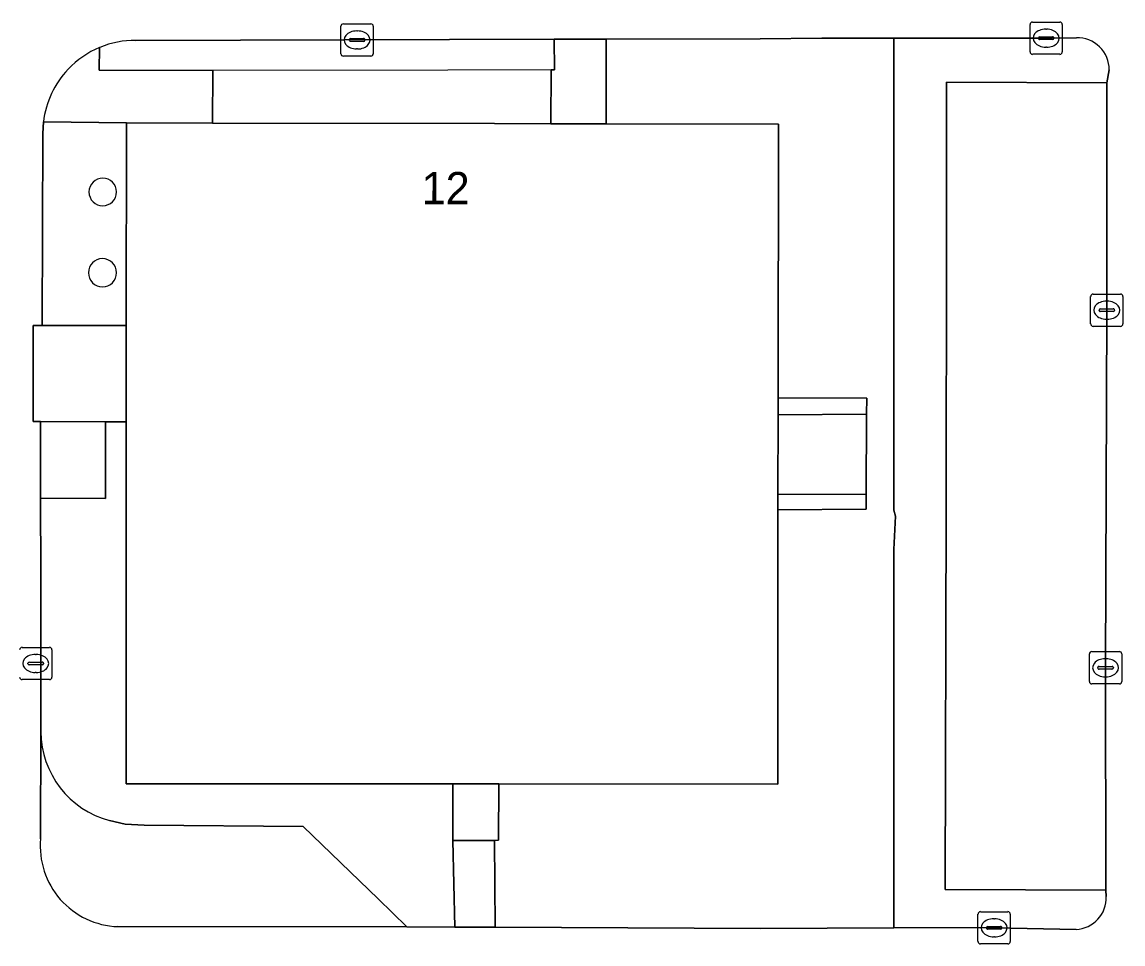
# Model space of a CAD drawing. Extents: x 161477 to 163040, y 383680 to 384871.
# Drawn here: x 161894.85 to 161928.97, y 384085.24 to 384113.8 of the extents above; entities that cross this region are included whole.
import ezdxf

# ---------------------------------------------------------------- set-up
doc = ezdxf.new("R2010")
doc.units = 0
for name, color, linetype in [('IMGEO_Dek', 7, 'Continuous'), ('IMGEO_Groenvoorziening', 7, 'Continuous'), ('IMGEO_Kolk', 7, 'Continuous'), ('IMGEO_Opslagtank', 7, 'Continuous'), ('IMGEO_Pand', 7, 'Continuous'), ('IMGEO_Pand_nummerreeks', 7, 'Continuous'), ('IMGEO_Parkeervlak_open', 7, 'Continuous'), ('IMGEO_Rijbaan_lokaal_open', 7, 'Continuous'), ('IMGEO_Voetpad_halfverhard', 7, 'Continuous'), ('IMGEO_Voetpad_op_trap', 7, 'Continuous'), ('IMGEO_Voetpad_open', 7, 'Continuous')]:
    doc.layers.add(name, color=color, linetype=linetype)

msp = doc.modelspace()

# ---------------------------------------------------------------- linework, layer by layer
at = {"layer": 'IMGEO_Dek'}
msp.add_lwpolyline([(161911.242, 384112.317), (161908.043, 384112.311), (161900.763, 384112.296), (161900.748, 384110.668), (161909.493, 384110.653), (161911.237, 384110.65)], close=True, dxfattribs=at)
at = {"layer": 'IMGEO_Groenvoorziening'}
for points in [[(161897.254, 384113.012), (161897.243, 384112.304), (161900.763, 384112.296), (161900.748, 384110.668), (161909.493, 384110.653), (161911.237, 384110.65), (161911.242, 384112.317), (161911.352, 384112.315), (161911.338, 384113.266)], [(161911.338, 384113.266), (161898.379, 384113.23)], [(161927.523, 384113.312), (161926.587, 384113.3), (161921.866, 384113.297), (161921.866, 384101.655), (161921.866, 384099.154), (161921.866, 384098.677), (161921.918, 384098.494), (161921.866, 384097.461), (161921.866, 384085.737), (161924.475, 384085.751), (161927.512, 384085.687)], [(161923.503, 384107.023), (161923.498, 384111.939), (161928.47, 384111.914), (161928.542, 384112.318)], [(161928.451, 384086.709), (161928.44, 384086.908), (161923.462, 384086.921), (161923.483, 384098.676), (161923.503, 384107.023)]]:
    msp.add_lwpolyline(points, dxfattribs=at)
for centre, radius, start, end in [((161898.35, 384110.369), 2.861, 89.4148, 112.5186), ((161927.55, 384112.32), 0.992, 359.8798, 91.5432), ((161927.46, 384086.677), 0.991, 272.9889, 1.8583)]:
    msp.add_arc(centre, radius, start, end, dxfattribs=at)
at = {"layer": 'IMGEO_Kolk'}
for p, q in [((161926.161, 384113.799), (161927.013, 384113.799)), ((161904.731, 384112.818), (161904.731, 384113.67)), ((161904.806, 384113.744), (161905.658, 384113.744)), ((161905.219, 384113.524), (161905.244, 384113.524)), ((161905.732, 384113.67), (161905.732, 384112.818)), ((161926.086, 384112.873), (161926.086, 384113.725)), ((161926.574, 384113.579), (161926.599, 384113.579)), ((161927.087, 384113.725), (161927.087, 384112.873)), ((161904.99, 384113.238), (161904.99, 384113.25)), ((161905.428, 384113.201), (161905.03, 384113.201)), ((161905.033, 384113.287), (161905.431, 384113.287)), ((161905.474, 384113.25), (161905.474, 384113.238)), ((161926.345, 384113.293), (161926.345, 384113.305)), ((161926.783, 384113.256), (161926.385, 384113.256)), ((161926.388, 384113.342), (161926.786, 384113.342)), ((161926.829, 384113.305), (161926.829, 384113.293)), ((161905.658, 384112.744), (161904.806, 384112.744)), ((161905.242, 384112.964), (161905.217, 384112.964)), ((161927.013, 384112.799), (161926.161, 384112.799)), ((161926.597, 384113.019), (161926.572, 384113.019)), ((161927.966, 384104.446), (161927.966, 384105.298)), ((161928.041, 384105.372), (161928.893, 384105.372)), ((161928.967, 384105.298), (161928.967, 384104.446)), ((161928.268, 384104.915), (161928.666, 384104.915)), ((161928.454, 384105.152), (161928.479, 384105.152)), ((161928.225, 384104.866), (161928.225, 384104.878)), ((161928.663, 384104.829), (161928.265, 384104.829)), ((161928.477, 384104.592), (161928.452, 384104.592)), ((161928.709, 384104.878), (161928.709, 384104.866)), ((161928.893, 384104.372), (161928.041, 384104.372)), ((161894.848, 384094.428), (161895.7, 384094.428)), ((161895.774, 384094.354), (161895.774, 384093.502)), ((161895.075, 384093.971), (161895.473, 384093.971)), ((161895.261, 384094.208), (161895.286, 384094.208)), ((161927.928, 384093.37), (161927.928, 384094.222)), ((161928.003, 384094.296), (161928.855, 384094.296)), ((161928.416, 384094.076), (161928.441, 384094.076)), ((161928.929, 384094.222), (161928.929, 384093.37)), ((161895.032, 384093.922), (161895.032, 384093.934)), ((161895.47, 384093.885), (161895.072, 384093.885)), ((161895.284, 384093.648), (161895.259, 384093.648)), ((161895.516, 384093.934), (161895.516, 384093.922)), ((161928.187, 384093.79), (161928.187, 384093.802)), ((161928.625, 384093.753), (161928.227, 384093.753)), ((161928.23, 384093.839), (161928.628, 384093.839)), ((161928.671, 384093.802), (161928.671, 384093.79)), ((161895.7, 384093.428), (161894.848, 384093.428)), ((161928.855, 384093.296), (161928.003, 384093.296)), ((161928.439, 384093.516), (161928.414, 384093.516)), ((161924.474, 384085.313), (161924.474, 384086.165)), ((161924.549, 384086.239), (161925.401, 384086.239)), ((161925.475, 384086.165), (161925.475, 384085.313)), ((161924.776, 384085.782), (161925.174, 384085.782)), ((161924.962, 384086.019), (161924.987, 384086.019)), ((161924.733, 384085.733), (161924.733, 384085.745)), ((161925.171, 384085.696), (161924.773, 384085.696)), ((161924.985, 384085.459), (161924.96, 384085.459)), ((161925.217, 384085.745), (161925.217, 384085.733)), ((161925.401, 384085.239), (161924.549, 384085.239))]:
    msp.add_line(p, q, dxfattribs=at)
for points in [[(161926.161, 384113.799), (161927.013, 384113.799)], [(161904.731, 384112.818), (161904.731, 384113.67)], [(161904.806, 384113.744), (161905.658, 384113.744)], [(161905.732, 384113.67), (161905.732, 384112.818)], [(161926.086, 384112.873), (161926.086, 384113.725)], [(161927.087, 384113.725), (161927.087, 384112.873)], [(161905.658, 384112.744), (161904.806, 384112.744)], [(161927.013, 384112.799), (161926.161, 384112.799)], [(161927.966, 384104.446), (161927.966, 384105.298)], [(161928.041, 384105.372), (161928.893, 384105.372)], [(161928.967, 384105.298), (161928.967, 384104.446)], [(161928.893, 384104.372), (161928.041, 384104.372)], [(161894.848, 384094.428), (161895.7, 384094.428)], [(161895.774, 384094.354), (161895.774, 384093.502)], [(161927.928, 384093.37), (161927.928, 384094.222)], [(161928.003, 384094.296), (161928.855, 384094.296)], [(161928.929, 384094.222), (161928.929, 384093.37)], [(161895.7, 384093.428), (161894.848, 384093.428)], [(161928.855, 384093.296), (161928.003, 384093.296)], [(161924.474, 384085.313), (161924.474, 384086.165)], [(161924.549, 384086.239), (161925.401, 384086.239)], [(161925.475, 384086.165), (161925.475, 384085.313)], [(161925.401, 384085.239), (161924.549, 384085.239)]]:
    msp.add_lwpolyline(points, dxfattribs=at)
for centre, radius, start, end in [((161926.163, 384113.723), 0.0765, 91.552, 178.448), ((161926.163, 384113.723), 0.0765, 91.552, 178.448), ((161927.011, 384113.723), 0.0765, 1.552, 88.448), ((161927.011, 384113.723), 0.0765, 1.552, 88.448), ((161904.808, 384113.668), 0.0765, 91.552, 178.448), ((161904.808, 384113.668), 0.0765, 91.552, 178.448), ((161905.656, 384113.668), 0.0765, 1.552, 88.448), ((161905.656, 384113.668), 0.0765, 1.552, 88.448), ((161905.03, 384113.247), 0.0403, 85.8775, 175.7526), ((161905.027, 384113.237), 0.0366, 178.938, 274.7102), ((161905.431, 384113.244), 0.043, 264.8664, 352.4533), ((161905.435, 384113.249), 0.0386, 1.7309, 96.639), ((161926.385, 384113.302), 0.0403, 85.8775, 175.7526), ((161926.382, 384113.292), 0.0366, 178.938, 274.7102), ((161926.786, 384113.299), 0.043, 264.8664, 352.4533), ((161926.79, 384113.304), 0.0386, 1.7309, 96.639), ((161904.808, 384112.82), 0.0765, 181.552, 268.448), ((161904.808, 384112.82), 0.0765, 181.552, 268.448), ((161905.656, 384112.82), 0.0765, 271.552, 358.448), ((161905.656, 384112.82), 0.0765, 271.552, 358.448), ((161926.163, 384112.875), 0.0765, 181.552, 268.448), ((161926.163, 384112.875), 0.0765, 181.552, 268.448), ((161927.011, 384112.875), 0.0765, 271.552, 358.448), ((161927.011, 384112.875), 0.0765, 271.552, 358.448), ((161928.043, 384105.296), 0.0765, 91.552, 178.448), ((161928.043, 384105.296), 0.0765, 91.552, 178.448), ((161928.891, 384105.296), 0.0765, 1.552, 88.448), ((161928.891, 384105.296), 0.0765, 1.552, 88.448), ((161928.265, 384104.875), 0.0403, 85.8775, 175.7526), ((161928.67, 384104.877), 0.0386, 1.7309, 96.639), ((161928.262, 384104.865), 0.0366, 178.938, 274.7102), ((161928.666, 384104.872), 0.043, 264.8664, 352.4533), ((161928.043, 384104.448), 0.0765, 181.552, 268.448), ((161928.043, 384104.448), 0.0765, 181.552, 268.448), ((161928.891, 384104.448), 0.0765, 271.552, 358.448), ((161928.891, 384104.448), 0.0765, 271.552, 358.448), ((161894.85, 384094.352), 0.0765, 91.552, 178.448), ((161894.85, 384094.352), 0.0765, 91.552, 178.448), ((161895.698, 384094.352), 0.0765, 1.552, 88.448), ((161895.698, 384094.352), 0.0765, 1.552, 88.448), ((161895.072, 384093.931), 0.0403, 85.8775, 175.7526), ((161895.477, 384093.933), 0.0386, 1.7309, 96.639), ((161928.005, 384094.22), 0.0765, 91.552, 178.448), ((161928.005, 384094.22), 0.0765, 91.552, 178.448), ((161928.853, 384094.22), 0.0765, 1.552, 88.448), ((161928.853, 384094.22), 0.0765, 1.552, 88.448), ((161895.069, 384093.921), 0.0366, 178.938, 274.7102), ((161895.473, 384093.928), 0.043, 264.8664, 352.4533), ((161928.227, 384093.799), 0.0403, 85.8775, 175.7526), ((161928.224, 384093.789), 0.0366, 178.938, 274.7102), ((161928.628, 384093.796), 0.043, 264.8664, 352.4533), ((161928.632, 384093.801), 0.0386, 1.7309, 96.639), ((161894.85, 384093.504), 0.0765, 181.552, 268.448), ((161894.85, 384093.504), 0.0765, 181.552, 268.448), ((161895.698, 384093.504), 0.0765, 271.552, 358.448), ((161895.698, 384093.504), 0.0765, 271.552, 358.448), ((161928.005, 384093.372), 0.0765, 181.552, 268.448), ((161928.005, 384093.372), 0.0765, 181.552, 268.448), ((161928.853, 384093.372), 0.0765, 271.552, 358.448), ((161928.853, 384093.372), 0.0765, 271.552, 358.448), ((161924.551, 384086.163), 0.0765, 91.552, 178.448), ((161924.551, 384086.163), 0.0765, 91.552, 178.448), ((161925.399, 384086.163), 0.0765, 1.552, 88.448), ((161925.399, 384086.163), 0.0765, 1.552, 88.448), ((161924.773, 384085.742), 0.0403, 85.8775, 175.7526), ((161925.178, 384085.744), 0.0386, 1.7309, 96.639), ((161924.77, 384085.732), 0.0366, 178.938, 274.7102), ((161925.174, 384085.739), 0.043, 264.8664, 352.4533), ((161924.551, 384085.315), 0.0765, 181.552, 268.448), ((161924.551, 384085.315), 0.0765, 181.552, 268.448), ((161925.399, 384085.315), 0.0765, 271.552, 358.448), ((161925.399, 384085.315), 0.0765, 271.552, 358.448)]:
    msp.add_arc(centre, radius, start, end, dxfattribs=at)
for centre, major_axis, ratio, start_param, end_param in [((161905.218, 384113.244), (-0.387, 0.002), 0.722429, 4.712389, 7.853982), ((161905.243, 384113.244), (-0.39, 0.002), 0.717154, 1.570796, 4.712389), ((161926.573, 384113.299), (-0.387, 0.002), 0.722429, 4.712389, 7.853982), ((161926.598, 384113.299), (-0.39, 0.002), 0.717154, 1.570796, 4.712389), ((161928.453, 384104.872), (-0.387, 0.002), 0.722429, 4.712389, 7.853982), ((161928.478, 384104.872), (-0.39, 0.002), 0.717154, 1.570796, 4.712389), ((161895.26, 384093.928), (-0.387, 0.002), 0.722429, 4.712389, 7.853982), ((161895.285, 384093.928), (-0.39, 0.002), 0.717154, 1.570796, 4.712389), ((161928.415, 384093.796), (-0.387, 0.002), 0.722429, 4.712389, 7.853982), ((161928.44, 384093.796), (-0.39, 0.002), 0.717154, 1.570796, 4.712389), ((161924.961, 384085.739), (-0.387, 0.002), 0.722429, 4.712389, 7.853982), ((161924.986, 384085.739), (-0.39, 0.002), 0.717154, 1.570796, 4.712389)]:
    msp.add_ellipse(centre, major_axis=major_axis, ratio=ratio, start_param=start_param, end_param=end_param, dxfattribs=at)
at = {"layer": 'IMGEO_Opslagtank'}
for centre, radius, start, end in [((161897.351, 384108.535), 0.428, 359.933, 269.933), ((161897.35, 384108.536), 0.428, 270.0648, 359.8012), ((161897.342, 384106.033), 0.437, 90.0656, 359.9344), ((161897.341, 384106.032), 0.437, 0.0025, 89.9975)]:
    msp.add_arc(centre, radius, start, end, dxfattribs=at)
at = {"layer": 'IMGEO_Pand'}
msp.add_lwpolyline([(161918.278, 384101.63), (161918.279, 384102.154), (161918.288, 384110.637), (161912.952, 384110.647), (161911.237, 384110.65), (161909.493, 384110.653), (161900.748, 384110.668), (161898.081, 384110.673), (161898.08, 384104.395), (161898.079, 384101.41), (161898.078, 384096.699), (161898.078, 384094.245), (161898.077, 384090.199), (161908.204, 384090.196), (161909.624, 384090.196), (161918.266, 384090.194), (161918.275, 384098.69), (161918.276, 384099.17)], close=True, dxfattribs=at)
at = {"layer": 'IMGEO_Parkeervlak_open'}
msp.add_lwpolyline([(161923.498, 384111.939), (161923.503, 384107.023), (161923.483, 384098.676), (161923.462, 384086.921), (161928.44, 384086.908), (161928.429, 384093.797), (161928.467, 384104.873), (161928.47, 384111.914)], close=True, dxfattribs=at)
for points in [[(161895.426, 384091.816), (161895.423, 384088.499)], [(161897.819, 384085.777), (161906.777, 384085.765), (161905.88, 384086.635), (161903.562, 384088.881), (161898.637, 384088.917), (161898.042, 384088.951), (161897.559, 384089.06)]]:
    msp.add_lwpolyline(points, dxfattribs=at)
for centre, radius, start, end in [((161898.31, 384091.844), 2.884, 180.5619, 254.9141), ((161897.905, 384088.268), 2.493, 174.6836, 268.0271)]:
    msp.add_arc(centre, radius, start, end, dxfattribs=at)
at = {"layer": 'IMGEO_Rijbaan_lokaal_open'}
for points in [[(161898.379, 384113.23), (161911.338, 384113.266), (161912.946, 384113.27), (161917.724, 384113.283), (161919.637, 384113.296), (161921.866, 384113.297), (161926.587, 384113.3), (161927.523, 384113.312)], [(161928.542, 384112.318), (161928.47, 384111.914), (161928.467, 384104.873), (161928.429, 384093.797), (161928.44, 384086.908), (161928.451, 384086.709)], [(161895.491, 384110.351), (161895.511, 384110.71)], [(161895.423, 384088.499), (161895.426, 384091.816), (161895.427, 384091.877), (161895.429, 384094.247), (161895.426, 384096.705), (161895.424, 384099.051), (161895.422, 384101.427), (161895.192, 384101.427), (161895.189, 384104.397), (161895.469, 384104.397), (161895.491, 384110.351)], [(161927.512, 384085.687), (161924.475, 384085.751), (161921.866, 384085.737), (161917.738, 384085.714), (161909.516, 384085.763), (161908.266, 384085.762), (161906.777, 384085.765), (161897.819, 384085.777)]]:
    msp.add_lwpolyline(points, dxfattribs=at)
for centre, radius, start, end in [((161898.35, 384110.369), 2.861, 89.4148, 112.5186), ((161927.55, 384112.32), 0.992, 359.8798, 91.5432), ((161898.349, 384110.382), 2.849, 112.6072, 136.7222), ((161898.348, 384110.368), 2.857, 136.506, 173.1325), ((161897.905, 384088.268), 2.493, 174.6836, 268.0271), ((161927.46, 384086.677), 0.991, 272.9889, 1.8583)]:
    msp.add_arc(centre, radius, start, end, dxfattribs=at)
at = {"layer": 'IMGEO_Voetpad_halfverhard'}
for points in [[(161921.866, 384097.461), (161921.918, 384098.494), (161921.866, 384098.677), (161921.866, 384099.154), (161921.866, 384101.655), (161921.866, 384113.297), (161919.637, 384113.296), (161917.724, 384113.283), (161912.946, 384113.27), (161912.948, 384112.29), (161912.952, 384110.647), (161918.288, 384110.637), (161918.279, 384102.154), (161921.026, 384102.142), (161921.023, 384101.649), (161921.009, 384099.158), (161921.006, 384098.71), (161918.275, 384098.69), (161918.266, 384090.194), (161909.624, 384090.196), (161909.615, 384088.454), (161909.494, 384088.441), (161909.516, 384085.763), (161917.738, 384085.714), (161921.866, 384085.737)], [(161898.081, 384110.673), (161895.511, 384110.71), (161895.491, 384110.351), (161895.469, 384104.397), (161898.08, 384104.395)]]:
    msp.add_lwpolyline(points, close=True, dxfattribs=at)
for points in [[(161898.078, 384096.699), (161898.079, 384101.41), (161897.439, 384101.411), (161897.434, 384099.035), (161895.424, 384099.051), (161895.426, 384096.705), (161895.429, 384094.247), (161895.427, 384091.877), (161895.426, 384091.816)], [(161897.559, 384089.06), (161898.042, 384088.951), (161898.637, 384088.917), (161903.562, 384088.881), (161905.88, 384086.635), (161906.777, 384085.765), (161908.266, 384085.762), (161908.195, 384088.44), (161908.204, 384090.196), (161898.077, 384090.199), (161898.078, 384094.245), (161898.078, 384096.699)]]:
    msp.add_lwpolyline(points, dxfattribs=at)
for centre, radius, start, end in [((161897.351, 384108.535), 0.428, 359.933, 269.933), ((161897.35, 384108.536), 0.428, 270.0648, 359.8012), ((161897.342, 384106.033), 0.437, 90.0656, 359.9344), ((161897.341, 384106.032), 0.437, 0.0025, 89.9975), ((161898.31, 384091.844), 2.884, 180.5619, 254.9141)]:
    msp.add_arc(centre, radius, start, end, dxfattribs=at)
at = {"layer": 'IMGEO_Voetpad_op_trap'}
for points in [[(161918.279, 384102.154), (161918.278, 384101.63), (161921.023, 384101.649), (161921.026, 384102.142)], [(161921.009, 384099.158), (161918.276, 384099.17), (161918.275, 384098.69), (161921.006, 384098.71)], [(161909.624, 384090.196), (161908.204, 384090.196), (161908.195, 384088.44), (161909.494, 384088.441), (161909.615, 384088.454)]]:
    msp.add_lwpolyline(points, close=True, dxfattribs=at)
at = {"layer": 'IMGEO_Voetpad_open'}
for points in [[(161912.948, 384112.29), (161912.946, 384113.27), (161911.338, 384113.266), (161911.352, 384112.315), (161911.242, 384112.317), (161911.237, 384110.65), (161912.952, 384110.647)], [(161911.242, 384112.317), (161908.043, 384112.311), (161900.763, 384112.296), (161900.748, 384110.668), (161909.493, 384110.653), (161911.237, 384110.65)], [(161898.08, 384104.395), (161895.469, 384104.397), (161895.189, 384104.397), (161895.192, 384101.427), (161895.422, 384101.427), (161897.439, 384101.411), (161898.079, 384101.41)], [(161921.023, 384101.649), (161918.278, 384101.63), (161918.276, 384099.17), (161921.009, 384099.158)], [(161897.439, 384101.411), (161895.422, 384101.427), (161895.424, 384099.051), (161897.434, 384099.035)], [(161909.494, 384088.441), (161908.195, 384088.44), (161908.266, 384085.762), (161909.516, 384085.763)]]:
    msp.add_lwpolyline(points, close=True, dxfattribs=at)
for points in [[(161900.763, 384112.296), (161897.243, 384112.304), (161897.254, 384113.012)], [(161895.511, 384110.71), (161898.081, 384110.673), (161900.748, 384110.668), (161900.763, 384112.296)]]:
    msp.add_lwpolyline(points, dxfattribs=at)
for centre, radius, start, end in [((161898.349, 384110.382), 2.849, 112.6072, 136.7222), ((161898.348, 384110.368), 2.857, 136.506, 173.1325)]:
    msp.add_arc(centre, radius, start, end, dxfattribs=at)

# ---------------------------------------------------------------- texts
at = {"layer": 'IMGEO_Pand_nummerreeks'}
msp.add_text('12', height=1, rotation=359.9026, dxfattribs=at).set_placement((161907.232, 384108.156))

doc.saveas('drawing.dxf')
